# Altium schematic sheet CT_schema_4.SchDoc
size 143 x 123 mm
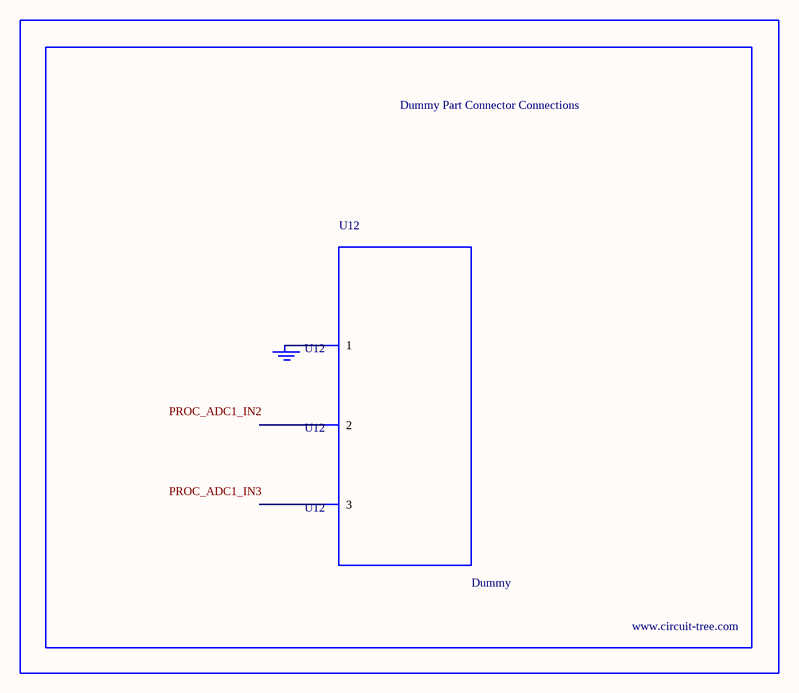
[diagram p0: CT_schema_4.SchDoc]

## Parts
BORDER3  (no value)
GND_INSTANCE_3_0  (no value)
U12  Dummy  [DUMMY_PACKAGE_122]

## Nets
NetGND_INSTANCE_3_0_0: GND_INSTANCE_3_0.0(GND) U12.1

Not connected (* = marked no-connect by the designer): U12 2 3

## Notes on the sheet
- Labels drawn without touching a wire or pin: PROC_ADC1_IN2, PROC_ADC1_IN3

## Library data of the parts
BORDER3 = BORDER_PAGE3
GND_INSTANCE_3_0 = GND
